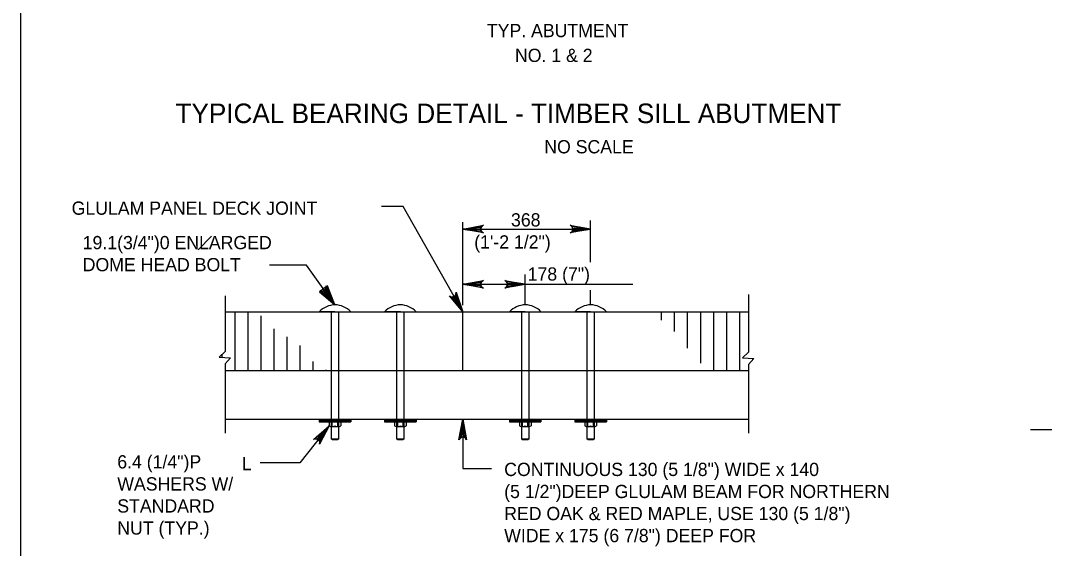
# Model space of a CAD drawing. Extents: x -8 to 75, y -110 to 0.
# Drawn here: x 35.75 to 45.04, y -77.67 to -72.88 of the extents above; entities that cross this region are included whole.
import ezdxf

# ---------------------------------------------------------------- set-up
doc = ezdxf.new("R2010")
doc.units = 0
for name, color, linetype in [('1', 7, 'Continuous'), ('2', 7, 'Continuous'), ('3', 7, 'Continuous'), ('5', 7, 'Continuous')]:
    doc.layers.add(name, color=color, linetype=linetype)

msp = doc.modelspace()

# ---------------------------------------------------------------- linework, layer by layer
at = {"layer": '1'}
msp.add_lwpolyline([(35.75, -87.25), (67.25, -87.25), (67.25, -66.75), (35.75, -66.75)], close=True, dxfattribs=at)
at = {"layer": '2'}
for p, q in [((38.3443, -75.1007), (38.0107, -75.1007)), ((38.6042, -75.4611), (38.3443, -75.1007)), ((37.6069, -75.3782), (37.6069, -75.8841)), ((42.3577, -75.368), (42.3577, -75.8902)), ((37.6069, -75.5248), (42.3577, -75.5248)), ((38.6042, -75.5248), (38.4615, -75.5248)), ((38.5727, -76.6775), (38.5727, -75.5248)), ((38.6042, -75.5248), (38.7469, -75.5248)), ((38.6357, -75.5248), (38.6357, -76.6775)), ((39.1661, -76.6775), (39.1661, -75.5248)), ((39.2291, -75.5248), (39.2291, -76.6775)), ((39.7642, -76.0563), (39.7642, -75.5248)), ((40.2993, -76.6775), (40.2993, -75.5248)), ((40.3623, -75.5248), (40.3623, -76.6775)), ((40.8927, -76.6775), (40.8927, -75.5248)), ((40.9557, -75.5248), (40.9557, -76.6775)), ((37.6069, -75.8841), (37.5517, -75.9362)), ((42.3577, -75.8902), (42.3024, -75.9422)), ((37.5517, -75.9362), (37.6557, -75.9419)), ((37.6557, -75.9419), (37.6069, -75.9965)), ((37.6069, -75.9965), (37.6069, -76.6243)), ((42.3024, -75.9422), (42.4064, -75.948)), ((42.4064, -75.948), (42.3577, -76.0025)), ((42.3577, -76.0025), (42.3577, -76.6243)), ((37.6069, -76.0563), (42.3577, -76.0563)), ((37.6069, -76.4972), (42.3577, -76.4972)), ((38.552, -76.5209), (38.552, -76.5565)), ((38.6564, -76.5209), (38.552, -76.5209)), ((38.552, -76.5565), (38.5671, -76.5652)), ((38.5671, -76.5652), (38.6412, -76.5652)), ((38.5796, -76.5652), (38.5796, -76.5209)), ((38.6288, -76.5652), (38.6288, -76.5209)), ((38.6412, -76.5652), (38.6564, -76.5565)), ((38.6564, -76.5209), (38.6564, -76.5565)), ((39.2497, -76.5209), (39.1454, -76.5209)), ((39.1454, -76.5209), (39.1454, -76.5565)), ((39.1454, -76.5565), (39.1605, -76.5652)), ((39.1605, -76.5652), (39.2347, -76.5652)), ((39.173, -76.5652), (39.173, -76.5209)), ((39.2222, -76.5652), (39.2222, -76.5209)), ((39.2347, -76.5652), (39.2497, -76.5565)), ((39.2497, -76.5209), (39.2497, -76.5565)), ((40.383, -76.5209), (40.2786, -76.5209)), ((40.2786, -76.5209), (40.2786, -76.5565)), ((40.2786, -76.5565), (40.2937, -76.5652)), ((40.2937, -76.5652), (40.3679, -76.5652)), ((40.3062, -76.5652), (40.3062, -76.5209)), ((40.3554, -76.5652), (40.3554, -76.5209)), ((40.3679, -76.5652), (40.383, -76.5565)), ((40.383, -76.5209), (40.383, -76.5565)), ((40.9764, -76.5209), (40.872, -76.5209)), ((40.872, -76.5209), (40.872, -76.5565)), ((40.872, -76.5565), (40.8871, -76.5652)), ((40.8871, -76.5652), (40.9612, -76.5652)), ((40.8996, -76.5652), (40.8996, -76.5209)), ((40.9488, -76.5652), (40.9488, -76.5209)), ((40.9612, -76.5652), (40.9764, -76.5565)), ((40.9764, -76.5209), (40.9764, -76.5565)), ((38.5805, -76.6853), (38.5727, -76.6775)), ((38.6357, -76.6775), (38.5727, -76.6775)), ((38.6278, -76.6853), (38.5805, -76.6853)), ((38.6357, -76.6775), (38.6278, -76.6853)), ((39.2291, -76.6775), (39.1661, -76.6775)), ((39.1739, -76.6853), (39.1661, -76.6775)), ((39.2212, -76.6853), (39.1739, -76.6853)), ((39.2291, -76.6775), (39.2212, -76.6853)), ((40.3623, -76.6775), (40.2993, -76.6775)), ((40.3072, -76.6853), (40.2993, -76.6775)), ((40.3545, -76.6853), (40.3072, -76.6853)), ((40.3623, -76.6775), (40.3545, -76.6853)), ((40.9557, -76.6775), (40.8927, -76.6775)), ((40.9005, -76.6853), (40.8927, -76.6775)), ((40.9478, -76.6853), (40.9005, -76.6853)), ((40.9557, -76.6775), (40.9478, -76.6853))]:
    msp.add_line(p, q, dxfattribs=at)
msp.add_lwpolyline([(38.6042, -75.4611), (38.5354, -75.2887), (38.4624, -75.3414)], close=True, dxfattribs=at)
for centre, radius, start, end in [((38.6042, -75.6528), 0.1917, 41.87015, 138.12985), ((38.5781, -76.5219), 0.0434, 233, 307), ((38.6303, -76.5219), 0.0434, 233, 307), ((39.1715, -76.5219), 0.0434, 233, 307), ((39.2237, -76.5219), 0.0434, 233, 307), ((40.3047, -76.5219), 0.0434, 233, 307), ((40.3569, -76.5219), 0.0434, 233, 307), ((40.8981, -76.5219), 0.0434, 233, 307), ((40.9503, -76.5219), 0.0434, 233, 307)]:
    msp.add_arc(centre, radius, start, end, dxfattribs=at)
at = {"layer": '3'}
for p, q in [((37.3624, -74.9613), (37.485, -74.8387)), ((38.2863, -76.8937), (37.9239, -76.8937)), ((39.7642, -76.9455), (40.026, -76.9455))]:
    msp.add_line(p, q, dxfattribs=at)
for points in [[(39.7642, -75.5248), (39.2231, -74.5703), (39.0261, -74.5703)], [(38.6042, -75.4611), (38.4668, -75.3303), (38.4832, -75.3362), (38.4977, -75.3348), (38.5092, -75.3293), (38.518, -75.3203), (38.5238, -75.3069), (38.5235, -75.2894), (38.6042, -75.4611), (38.5238, -75.3069), (38.518, -75.3203), (38.6042, -75.4611), (38.5092, -75.3293), (38.4977, -75.3348), (38.6042, -75.4611), (38.4832, -75.3362)], [(39.7642, -75.5248), (39.6422, -75.3795), (39.658, -75.3872), (39.6726, -75.3875), (39.6844, -75.3832), (39.6942, -75.3752), (39.7016, -75.3627), (39.7032, -75.3452), (39.7642, -75.5248), (39.7016, -75.3627), (39.6942, -75.3752), (39.7642, -75.5248), (39.6844, -75.3832), (39.6726, -75.3875), (39.7642, -75.5248), (39.658, -75.3872)], [(38.552, -76.5565), (38.2862, -76.8937)], [(38.552, -76.5565), (38.4641, -76.7246), (38.4652, -76.7071), (38.4599, -76.6936), (38.4514, -76.6842), (38.4402, -76.6781), (38.4258, -76.6762), (38.4092, -76.6812), (38.552, -76.5565), (38.4258, -76.6762), (38.4402, -76.6781), (38.552, -76.5565), (38.4514, -76.6842), (38.4599, -76.6936), (38.552, -76.5565), (38.4652, -76.7071)], [(39.7642, -76.4972), (39.7991, -76.6837), (39.7892, -76.6693), (39.7767, -76.6619), (39.7642, -76.6598), (39.7517, -76.6619), (39.7392, -76.6693), (39.7293, -76.6837), (39.7642, -76.4972), (39.7392, -76.6693), (39.7517, -76.6619), (39.7642, -76.4972), (39.7642, -76.6598), (39.7767, -76.6619), (39.7642, -76.4972), (39.7892, -76.6693)], [(39.7642, -76.4972), (39.7642, -76.9454)]]:
    msp.add_lwpolyline(points, dxfattribs=at)
for points in [[(39.7642, -75.5248), (39.7616, -75.5207), (39.76, -75.5224)], [(38.552, -76.5565), (38.5482, -76.5595), (38.55, -76.5609)], [(39.7642, -76.4972), (39.763, -76.502), (39.7654, -76.502)]]:
    msp.add_lwpolyline(points, close=True, dxfattribs=at)
at = {"layer": '5'}
for p, q in [((39.7642, -75.4634), (39.7642, -74.7109)), ((40.9241, -75.0744), (40.9241, -74.6965)), ((39.7642, -75.4634), (39.7642, -74.7254)), ((39.7642, -74.7744), (40.9242, -74.7744)), ((40.9242, -74.7744), (40.9242, -74.7744)), ((39.7642, -75.4633), (39.7642, -75.0973)), ((40.3308, -75.4634), (40.3308, -75.1859)), ((39.7642, -75.2745), (41.3083, -75.2745)), ((40.3308, -75.2745), (40.3308, -75.2745)), ((40.9242, -75.4634), (40.9242, -75.3263)), ((37.698, -76.0562), (37.698, -75.5248)), ((37.8161, -76.0562), (37.8161, -75.5248)), ((39.1976, -75.5248), (39.0548, -75.5248)), ((39.1976, -75.5248), (39.3403, -75.5248)), ((39.7642, -75.5248), (39.7642, -75.5248)), ((40.3308, -75.5248), (40.1881, -75.5248)), ((40.3308, -75.5248), (40.3308, -75.5248)), ((40.3308, -75.5248), (40.4735, -75.5248)), ((40.9242, -75.5248), (40.7815, -75.5248)), ((40.9242, -75.5248), (40.9242, -75.5248)), ((40.9242, -75.5248), (41.0669, -75.5248)), ((41.5683, -75.5998), (41.5683, -75.5248)), ((41.6864, -75.7011), (41.6864, -75.5248)), ((41.8045, -75.8544), (41.8045, -75.5248)), ((41.9227, -75.9907), (41.9227, -75.5248)), ((42.0407, -76.054), (42.0407, -75.5248)), ((42.1588, -76.0563), (42.1588, -75.5248)), ((42.277, -76.0563), (42.277, -75.5248)), ((37.9342, -76.0562), (37.9342, -75.559)), ((38.0523, -76.0561), (38.0523, -75.6789)), ((38.1704, -76.056), (38.1704, -75.7506)), ((38.2886, -76.0559), (38.2886, -75.8284)), ((37.5799, -75.9377), (37.5799, -75.9096)), ((38.4067, -76.0558), (38.4067, -75.9742)), ((42.3951, -75.9607), (42.3951, -75.9473)), ((38.5247, -76.0558), (38.5247, -76.0512)), ((41.1697, -76.0563), (41.1697, -76.0563)), ((38.4615, -76.4972), (38.4615, -76.5209)), ((38.4615, -76.5091), (38.7469, -76.5091)), ((38.4615, -76.5209), (38.7469, -76.5209)), ((38.7469, -76.4972), (38.7469, -76.5209)), ((39.0548, -76.4972), (39.0548, -76.5209)), ((39.0548, -76.5091), (39.3403, -76.5091)), ((39.0548, -76.5209), (39.3403, -76.5209)), ((39.3403, -76.4972), (39.3403, -76.5209)), ((40.1881, -76.4972), (40.1881, -76.5209)), ((40.1881, -76.5091), (40.4735, -76.5091)), ((40.1881, -76.5209), (40.4735, -76.5209)), ((40.4735, -76.4972), (40.4735, -76.5209)), ((40.7815, -76.4972), (40.7815, -76.5209)), ((40.7815, -76.5091), (41.0669, -76.5091)), ((40.7815, -76.5209), (41.0669, -76.5209)), ((41.0669, -76.4972), (41.0669, -76.5209)), ((46.6245, -76.5931), (44.9167, -76.5931))]:
    msp.add_line(p, q, dxfattribs=at)
for points in [[(39.7642, -74.7744), (39.9506, -74.7395), (39.9363, -74.7494), (39.9288, -74.7619), (39.9267, -74.7744), (39.9288, -74.7869), (39.9363, -74.7994), (39.9506, -74.8093), (39.7642, -74.7744), (39.9363, -74.7994), (39.9288, -74.7869), (39.7642, -74.7744), (39.9267, -74.7744), (39.9288, -74.7619), (39.7642, -74.7744), (39.9363, -74.7494)], [(40.9242, -74.7744), (40.7377, -74.8093), (40.7521, -74.7994), (40.7595, -74.7869), (40.7617, -74.7744), (40.7595, -74.7619), (40.7521, -74.7494), (40.7377, -74.7395), (40.9242, -74.7744), (40.7521, -74.7494), (40.7595, -74.7619), (40.9242, -74.7744), (40.7617, -74.7744), (40.7595, -74.7869), (40.9242, -74.7744), (40.7521, -74.7994)], [(39.7642, -75.2745), (39.9506, -75.2396), (39.9363, -75.2495), (39.9288, -75.262), (39.9267, -75.2745), (39.9288, -75.287), (39.9363, -75.2995), (39.9506, -75.3094), (39.7642, -75.2745), (39.9363, -75.2995), (39.9288, -75.287), (39.7642, -75.2745), (39.9267, -75.2745), (39.9288, -75.262), (39.7642, -75.2745), (39.9363, -75.2495)], [(40.3308, -75.2745), (40.1444, -75.3094), (40.1587, -75.2995), (40.1662, -75.287), (40.1683, -75.2745), (40.1662, -75.262), (40.1587, -75.2495), (40.1444, -75.2396), (40.3308, -75.2745), (40.1587, -75.2495), (40.1662, -75.262), (40.3308, -75.2745), (40.1683, -75.2745), (40.1662, -75.287), (40.3308, -75.2745), (40.1587, -75.2995)]]:
    msp.add_lwpolyline(points, dxfattribs=at)
for points in [[(39.8823, -74.7547), (39.8823, -74.7941), (39.7642, -74.7744)], [(40.8061, -74.7547), (40.8061, -74.7941), (40.9242, -74.7744)], [(39.8823, -75.2548), (39.8823, -75.2942), (39.7642, -75.2745)], [(40.2127, -75.2548), (40.2127, -75.2942), (40.3308, -75.2745)]]:
    msp.add_lwpolyline(points, close=True, dxfattribs=at)
for centre in [(39.1976, -75.6528), (40.3308, -75.6528), (40.9242, -75.6528)]:
    msp.add_arc(centre, 0.1917, 41.87015, 138.12985, dxfattribs=at)

# ---------------------------------------------------------------- texts
at = {"layer": '2'}
msp.add_text('TYPICAL BEARING DETAIL - TIMBER SILL ABUTMENT', height=0.177167, dxfattribs=at).set_placement((37.1572, -73.8128))
at = {"layer": '3'}
for s, p in [('TYP. ABUTMENT', (39.9824, -73.0337)), ('NO. 1 & 2', (40.2374, -73.2586)), ('NO SCALE', (40.5033, -74.0872)), ('GLULAM PANEL DECK JOINT', (36.2143, -74.6442)), ('19.1(3/4")0 ENLARGED', (36.3147, -74.9564)), ('DOME HEAD BOLT', (36.3147, -75.1564)), ('6.4 (1/4")P', (36.6284, -76.9443)), ('L', (37.7586, -76.9608)), ('CONTINUOUS 130 (5 1/8") WIDE x 140', (40.1397, -77.0131)), ('WASHERS W/ ', (36.6284, -77.1443)), ('(5 1/2")DEEP GLULAM BEAM FOR NORTHERN', (40.1397, -77.2131)), ('STANDARD', (36.6284, -77.3443)), ('RED OAK & RED MAPLE, USE 130 (5 1/8")', (40.1397, -77.4131)), ('NUT (TYP.)', (36.6284, -77.5443)), ('WIDE x 175 (6 7/8") DEEP FOR', (40.1397, -77.6131))]:
    msp.add_text(s, height=0.12, dxfattribs=at).set_placement(p)
at = {"layer": '5'}
for s, p in [('368', (40.2015, -74.7503)), ('(1\'-2 1/2")', (39.8679, -74.9503)), ('178 (7")', (40.3527, -75.2411))]:
    msp.add_text(s, height=0.12, dxfattribs=at).set_placement(p)

doc.saveas('drawing.dxf')
